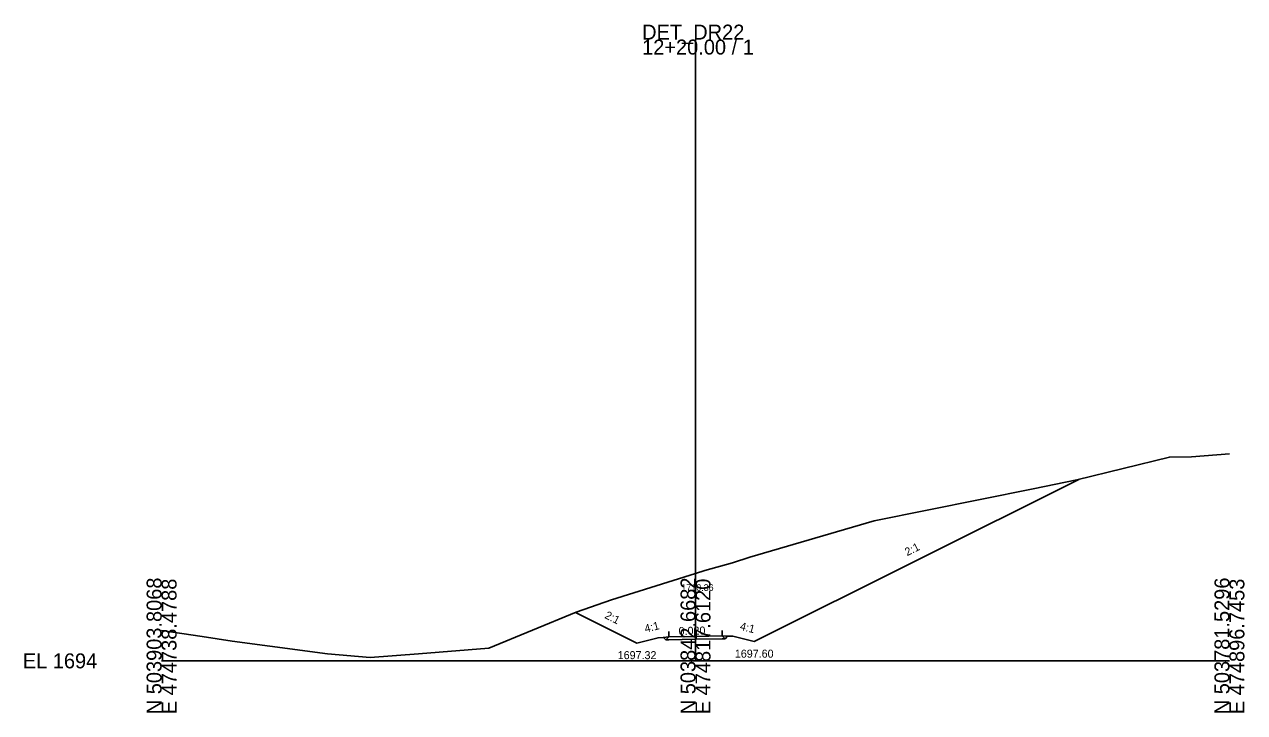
# Model space of a CAD drawing. Extents: x -26 to 1203, y -10 to 9633.
# Drawn here: x -25.7 to 202.8, y 5490.3 to 5619.2 of the extents above; entities that cross this region are included whole.
import ezdxf

# ---------------------------------------------------------------- set-up
doc = ezdxf.new("R2010")
doc.units = 0
for name, color, linetype in [('Exist Cross Section Cell', 7, 'Continuous'), ('Exist XS Center Line Elevation Label', 7, 'Continuous'), ('Exist XS Ground Line', 7, 'Continuous'), ('Prop XS Ditch Slope Text', 7, 'Continuous'), ('Prop XS Ditch Standard Text', 7, 'Continuous'), ('Prop XS Earthwork Shape', 7, 'Continuous'), ('Prop XS EOT Tick Mark', 7, 'Continuous'), ('Prop XS Finish Grade', 7, 'Continuous'), ('Prop XS Finish Grade Earthwork', 7, 'Continuous'), ('Prop XS Finish Grade Pavement', 7, 'Continuous'), ('Prop XS Pvmt Edge Slope', 7, 'Continuous'), ('Prop XS SE Text', 7, 'Continuous'), ('Prop XS Shoulder Borrow Shape', 7, 'Continuous'), ('Prop XS Side Slope Text', 7, 'Continuous'), ('Prop XS Subgrade Earthwork', 7, 'Continuous')]:
    doc.layers.add(name, color=color, linetype=linetype)

msp = doc.modelspace()

# ---------------------------------------------------------------- linework, layer by layer
at = {"layer": 'Exist Cross Section Cell'}
for p, q in [((100, 5500), (100, 5616.39)), ((0, 5500), (100, 5500)), ((100, 5500), (200, 5500))]:
    msp.add_line(p, q, dxfattribs=at)
at = {"layer": 'Exist XS Ground Line'}
msp.add_lwpolyline([(0, 5505.69), (7.61, 5504.54), (13.21, 5503.68), (20.25, 5502.74), (31.06, 5501.29), (39.05, 5500.62), (48.14, 5501.3), (61.29, 5502.37), (77.67, 5509.13), (84.26, 5511.46), (100, 5516.36), (101.74, 5516.9), (106.95, 5518.38), (110.17, 5519.44), (133.49, 5526.25), (163.25, 5532.23), (171.44, 5533.91), (188.75, 5538.18), (192.9, 5538.2), (200, 5538.8)], dxfattribs=at)
at = {"layer": 'Prop XS Earthwork Shape'}
msp.add_lwpolyline([(89, 5503.32), (77.52, 5509.06), (77.67, 5509.13), (84.26, 5511.46), (100, 5516.36), (101.74, 5516.9), (106.95, 5518.38), (110.17, 5519.44), (133.49, 5526.25), (163.25, 5532.23), (171.44, 5533.91), (171.77, 5533.99), (111, 5503.6), (107, 5504.6), (106.02, 5504.64), (105.53, 5504.15), (105, 5504.14), (100, 5504.04), (95, 5503.94), (94.45, 5503.93), (93.98, 5504.4), (93, 5504.32)], close=True, dxfattribs=at)
at = {"layer": 'Prop XS EOT Tick Mark'}
for p, q in [((95, 5504.48), (95, 5505.48)), ((105, 5504.68), (105, 5505.68))]:
    msp.add_line(p, q, dxfattribs=at)
at = {"layer": 'Prop XS Finish Grade'}
for p, q in [((95, 5504.48), (93.98, 5504.4)), ((105, 5504.68), (106.02, 5504.64))]:
    msp.add_line(p, q, dxfattribs=at)
at = {"layer": 'Prop XS Finish Grade Earthwork'}
for p, q in [((111, 5503.6), (171.77, 5533.99)), ((89, 5503.32), (77.52, 5509.06)), ((93, 5504.32), (89, 5503.32)), ((93.98, 5504.4), (93, 5504.32)), ((106.02, 5504.64), (107, 5504.6)), ((107, 5504.6), (111, 5503.6))]:
    msp.add_line(p, q, dxfattribs=at)
at = {"layer": 'Prop XS Finish Grade Pavement'}
for p, q in [((95, 5504.48), (100, 5504.58)), ((100, 5504.58), (105, 5504.68))]:
    msp.add_line(p, q, dxfattribs=at)
at = {"layer": 'Prop XS Pvmt Edge Slope'}
for p, q in [((95, 5504.48), (94.45, 5503.93)), ((105, 5504.68), (105.53, 5504.15))]:
    msp.add_line(p, q, dxfattribs=at)
at = {"layer": 'Prop XS Shoulder Borrow Shape'}
for points in [[(95, 5504.48), (94.45, 5503.93), (93.98, 5504.4)], [(105.53, 5504.15), (106.02, 5504.64), (105, 5504.68)]]:
    msp.add_lwpolyline(points, close=True, dxfattribs=at)
at = {"layer": 'Prop XS Subgrade Earthwork'}
for p, q in [((94.45, 5503.93), (93.98, 5504.4)), ((95, 5503.94), (94.45, 5503.93)), ((100, 5504.04), (95, 5503.94)), ((105, 5504.14), (100, 5504.04)), ((105, 5504.14), (105.53, 5504.15)), ((105.53, 5504.15), (106.02, 5504.64))]:
    msp.add_line(p, q, dxfattribs=at)

# ---------------------------------------------------------------- texts
at = {"layer": 'Exist Cross Section Cell'}
for s, p in [('DET_DR22', (90, 5616.39)), ('12+20.00 / 1', (90, 5613.59)), ('EL 1694', (-26, 5498.6))]:
    msp.add_text(s, height=2.8, dxfattribs=at).set_placement(p)
for s, p in [('N 503903.8068', (0, 5490)), ('E 474738.4788', (2.8, 5490)), ('N 503842.6682', (100, 5490)), ('E 474817.6120', (102.8, 5490)), ('N 503781.5296', (200, 5490)), ('E 474896.7453', (202.8, 5490))]:
    msp.add_text(s, height=2.8, rotation=90, dxfattribs=at).set_placement(p)
at = {"layer": 'Exist XS Center Line Elevation Label'}
msp.add_text('1710.36', height=1.25, dxfattribs=at).set_placement((97.35, 5513.11))
at = {"layer": 'Prop XS Ditch Slope Text'}
for rotation, p in [(14.0362, (90.64, 5505.28)), (345.9638, (108.21, 5505.85))]:
    msp.add_text('4:1', height=1.5, rotation=rotation, dxfattribs=at).set_placement(p)
at = {"layer": 'Prop XS Ditch Standard Text'}
for s, p in [('1697.32', (85.43, 5500.32)), ('1697.60', (107.37, 5500.6))]:
    msp.add_text(s, height=1.5, dxfattribs=at).set_placement(p)
at = {"layer": 'Prop XS SE Text'}
msp.add_text('0.020', height=1.5, rotation=1.1458, dxfattribs=at).set_placement((96.85, 5504.84))
at = {"layer": 'Prop XS Side Slope Text'}
for rotation, p in [(26.5651, (139.65, 5519.61)), (333.4349, (82.87, 5508.07))]:
    msp.add_text('2:1', height=1.5, rotation=rotation, dxfattribs=at).set_placement(p)

doc.saveas('drawing.dxf')
